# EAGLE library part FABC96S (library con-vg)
CONNECTOR female, 96 pins, block, type C, rows ABC, grid 2.54 mm
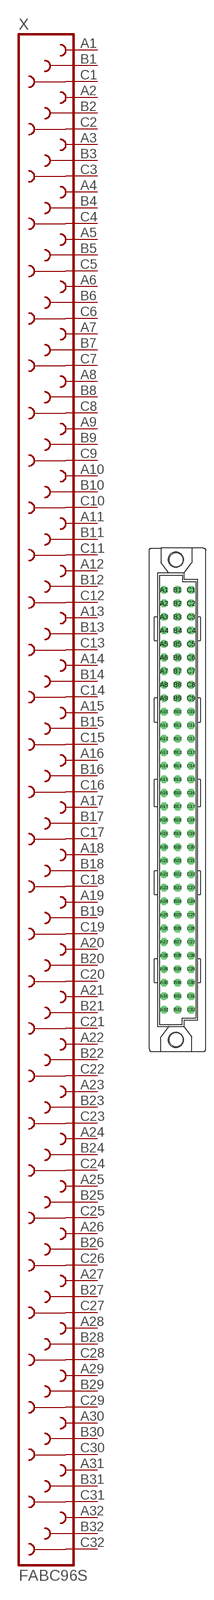
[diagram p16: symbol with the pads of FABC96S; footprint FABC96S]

Designator prefix X

## FABC96S  [FABC96S]
A1  A1  pas
A2  A2  pas
A3  A3  pas
A4  A4  pas
A5  A5  pas
A6  A6  pas
A7  A7  pas
A8  A8  pas
A9  A9  pas
A10  A10  pas
A11  A11  pas
A12  A12  pas
A13  A13  pas
A14  A14  pas
A15  A15  pas
A16  A16  pas
A17  A17  pas
A18  A18  pas
A19  A19  pas
A20  A20  pas
A21  A21  pas
A22  A22  pas
A23  A23  pas
A24  A24  pas
A25  A25  pas
A26  A26  pas
A27  A27  pas
A28  A28  pas
A29  A29  pas
A30  A30  pas
A31  A31  pas
A32  A32  pas
B1  B1  pas
B2  B2  pas
B3  B3  pas
B4  B4  pas
B5  B5  pas
B6  B6  pas
B7  B7  pas
B8  B8  pas
B9  B9  pas
B10  B10  pas
B11  B11  pas
B12  B12  pas
B13  B13  pas
B14  B14  pas
B15  B15  pas
B16  B16  pas
B17  B17  pas
B18  B18  pas
B19  B19  pas
B20  B20  pas
B21  B21  pas
B22  B22  pas
B23  B23  pas
B24  B24  pas
B25  B25  pas
B26  B26  pas
B27  B27  pas
B28  B28  pas
B29  B29  pas
B30  B30  pas
B31  B31  pas
B32  B32  pas
C1  C1  pas
C2  C2  pas
C3  C3  pas
C4  C4  pas
C5  C5  pas
C6  C6  pas
C7  C7  pas
C8  C8  pas
C9  C9  pas
C10  C10  pas
C11  C11  pas
C12  C12  pas
C13  C13  pas
C14  C14  pas
C15  C15  pas
C16  C16  pas
C17  C17  pas
C18  C18  pas
C19  C19  pas
C20  C20  pas
C21  C21  pas
C22  C22  pas
C23  C23  pas
C24  C24  pas
C25  C25  pas
C26  C26  pas
C27  C27  pas
C28  C28  pas
C29  C29  pas
C30  C30  pas
C31  C31  pas
C32  C32  pas

## Footprint FABC96S (pad centres in mm)
CONNECTOR female, 96 pins, type C, rows ABC, grid 2.54 mm
drill 0.914 octagon: A1 -2.54,39.37; A2 -2.54,36.83; A3 -2.54,34.29; A4 -2.54,31.75; A5 -2.54,29.21; A6 -2.54,26.67; A7 -2.54,24.13; A8 -2.54,21.59; A9 -2.54,19.05; A10 -2.54,16.51; A11 -2.54,13.97; A12 -2.54,11.43; A13 -2.54,8.89; A14 -2.54,6.35; A15 -2.54,3.81; A16 -2.54,1.27; A17 -2.54,-1.27; A18 -2.54,-3.81; A19 -2.54,-6.35; A20 -2.54,-8.89; A21 -2.54,-11.43; A22 -2.54,-13.97; A23 -2.54,-16.51; A24 -2.54,-19.05; A25 -2.54,-21.59; A26 -2.54,-24.13; A27 -2.54,-26.67; A28 -2.54,-29.21; A29 -2.54,-31.75; A30 -2.54,-34.29; A31 -2.54,-36.83; A32 -2.54,-39.37; B1 0,39.37; B2 0,36.83; B3 0,34.29; B4 0,31.75; B5 0,29.21; B6 0,26.67; B7 0,24.13; B8 0,21.59; B9 0,19.05; B10 0,16.51; B11 0,13.97; B12 0,11.43; B13 0,8.89; B14 0,6.35; B15 0,3.81; B16 0,1.27; B17 0,-1.27; B18 0,-3.81; B19 0,-6.35; B20 0,-8.89; B21 0,-11.43; B22 0,-13.97; B23 0,-16.51; B24 0,-19.05; B25 0,-21.59; B26 0,-24.13; B27 0,-26.67; B28 0,-29.21; B29 0,-31.75; B30 0,-34.29; B31 0,-36.83; B32 0,-39.37; C1 2.54,39.37; C2 2.54,36.83; C3 2.54,34.29; C4 2.54,31.75; C5 2.54,29.21; C6 2.54,26.67; C7 2.54,24.13; C8 2.54,21.59; C9 2.54,19.05; C10 2.54,16.51; C11 2.54,13.97; C12 2.54,11.43; C13 2.54,8.89; C14 2.54,6.35; C15 2.54,3.81; C16 2.54,1.27; C17 2.54,-1.27; C18 2.54,-3.81; C19 2.54,-6.35; C20 2.54,-8.89; C21 2.54,-11.43; C22 2.54,-13.97; C23 2.54,-16.51; C24 2.54,-19.05; C25 2.54,-21.59; C26 2.54,-24.13; C27 2.54,-26.67; C28 2.54,-29.21; C29 2.54,-31.75; C30 2.54,-34.29; C31 2.54,-36.83; C32 2.54,-39.37
hole 2.794 at -0.305,45.009
hole 2.794 at -0.305,-45.009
